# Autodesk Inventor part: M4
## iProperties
IsCustomPart: 0
Created: 2014-10
Part Number: M4
Material: Steel, Mild
Description: 6각머리 태핑 나사
Document SubType Name: Modeling
Standard: KS B 1003
Designer: KYOUNG IL JANG
Standards Organization: KS
Language: ko-KR
Size Designation: M 4 x 10
Categories: <MemberInstance><Categories><Category DisplayName="조임쇠" InternalName="e4da775c-781d-43d5-af7c-5136215cf5a6" Mnemonic="FSTN"><Category DisplayName="볼트" InternalN
Density: 7.86 g/cm^3
Mass: 2.0371 g
Surface Area: 3.0572 cm^2
Volume: 0.259174 cm^3
Author: SeoGD™ [www.esajin.kr]
Revision Number: 1
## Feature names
1. Fillet2
